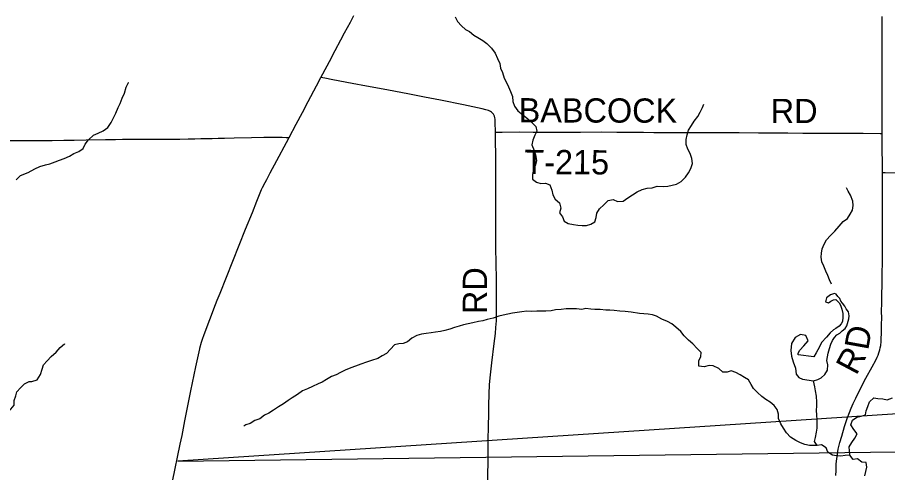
# Model space of a CAD drawing. Extents: x 0 to 34, y 0 to 22.
# Drawn here: x 15.659 to 17.698, y 13.231 to 14.297 of the extents above; entities that cross this region are included whole.
import ezdxf

# ---------------------------------------------------------------- set-up
doc = ezdxf.new("R2010")
doc.units = 0
for name, color, linetype in [('GM_X_County_Road', 7, 'Continuous'), ('GM_X_County_Road_Text', 7, 'Continuous'), ('GM_X_Minor_Lake', 7, 'Continuous'), ('GM_X_Minor_River', 7, 'Continuous'), ('GM_X_State_Route', 7, 'Continuous'), ('GM_X_Township_Road', 7, 'Continuous'), ('GM_X_Township_Road_Text', 7, 'Continuous'), ('SH_Text', 7, 'Continuous')]:
    doc.layers.add(name, color=color, linetype=linetype)

msp = doc.modelspace()

# ---------------------------------------------------------------- linework, layer by layer
at = {"layer": 'GM_X_County_Road'}
for points in [[(17.6856, 14.0251), (17.6855, 14.0542), (17.6855, 14.0673), (17.6855, 14.0716), (17.6854, 14.076), (17.6854, 14.0946), (17.6855, 14.1079), (17.6854, 14.1401), (17.6854, 14.1653), (17.6854, 14.1884), (17.6853, 14.205), (17.6856, 14.224), (17.6856, 14.2361), (17.6856, 14.2485), (17.6854, 14.2795), (17.6855, 14.2901), (17.6857, 14.2988)], [(15.6401, 14.0085), (15.6599, 14.0087), (15.6835, 14.0088), (15.722, 14.0087), (15.7407, 14.0087), (15.7674, 14.009), (15.7916, 14.0093), (15.8202, 14.0098), (15.8656, 14.0105), (15.8886, 14.0109), (15.9054, 14.0113), (15.9127, 14.0115), (15.9243, 14.0116), (15.9341, 14.0116), (15.9396, 14.0115), (15.952, 14.0115), (15.9731, 14.0118), (15.9849, 14.0119), (16.0115, 14.0118), (16.0394, 14.012), (16.0593, 14.0123), (16.0748, 14.0126), (16.0891, 14.0128), (16.1059, 14.0133), (16.1157, 14.0135), (16.1293, 14.0138), (16.1441, 14.014), (16.1667, 14.0144), (16.2076, 14.0153), (16.2363, 14.0161), (16.2595, 14.0161), (16.2794, 14.0161), (16.2887, 14.0157), (16.2956, 14.0153)], [(17.6863, 13.9338), (17.6861, 13.9531), (17.6861, 13.9654), (17.6858, 13.9772), (17.6858, 13.9921), (17.6857, 14.012), (17.6857, 14.0195), (17.6856, 14.0251)], [(17.5771, 13.224), (17.5774, 13.2353), (17.578, 13.2512), (17.579, 13.2628), (17.5805, 13.2738), (17.5826, 13.2859), (17.5864, 13.3009), (17.5906, 13.3162), (17.5976, 13.3389), (17.6037, 13.3578), (17.6089, 13.3715), (17.6132, 13.3819), (17.6178, 13.3924), (17.6238, 13.4048), (17.6302, 13.4183), (17.6473, 13.4522), (17.6619, 13.4788), (17.6704, 13.4938), (17.6739, 13.501), (17.676, 13.5059), (17.6779, 13.511), (17.6801, 13.518), (17.6812, 13.523), (17.6822, 13.5281), (17.6827, 13.5318), (17.6829, 13.5348), (17.6832, 13.5373), (17.6833, 13.5399), (17.6833, 13.5422), (17.6835, 13.5456), (17.6838, 13.5555), (17.6841, 13.5673), (17.6843, 13.5792), (17.6845, 13.5919), (17.6843, 13.6092), (17.6845, 13.6267), (17.6849, 13.6455), (17.6854, 13.6725), (17.6857, 13.6983), (17.686, 13.722), (17.6863, 13.7553), (17.6863, 13.7823), (17.6865, 13.8032), (17.6865, 13.8217), (17.6864, 13.8546), (17.6865, 13.873), (17.6865, 13.9084), (17.6863, 13.9326), (17.6863, 13.9338)]]:
    msp.add_lwpolyline(points, dxfattribs=at)
at = {"layer": 'GM_X_Minor_Lake'}
msp.add_line((17.4986, 13.4496), (17.5248, 13.4454), dxfattribs=at)
msp.add_lwpolyline([(17.5248, 13.4454), (17.5346, 13.4485), (17.5429, 13.4528), (17.5515, 13.4605), (17.5574, 13.4708), (17.5581, 13.483), (17.556, 13.4936), (17.5589, 13.5107), (17.5622, 13.521), (17.5655, 13.5313), (17.5695, 13.5404), (17.574, 13.5473), (17.5792, 13.5531), (17.5864, 13.5574), (17.592, 13.5627), (17.5988, 13.5685), (17.6029, 13.5746), (17.6039, 13.5803), (17.6072, 13.591), (17.6079, 13.5982), (17.6063, 13.6073), (17.6013, 13.6141), (17.5982, 13.6205), (17.5924, 13.6277), (17.5886, 13.6326), (17.5863, 13.6386), (17.582, 13.6435), (17.5778, 13.6484), (17.5736, 13.6502), (17.5691, 13.6483), (17.5646, 13.6467), (17.5612, 13.6444), (17.5552, 13.6401), (17.553, 13.631), (17.5595, 13.6284), (17.5651, 13.6319), (17.5715, 13.6354), (17.5772, 13.6362), (17.5848, 13.6287), (17.5876, 13.6227), (17.5907, 13.6132), (17.5935, 13.6034), (17.5932, 13.595), (17.5925, 13.5848), (17.5896, 13.579), (17.5847, 13.574), (17.5772, 13.5686), (17.5712, 13.5651), (17.5633, 13.5578), (17.5554, 13.5483), (17.5435, 13.5352), (17.5383, 13.5253), (17.5309, 13.5115), (17.5257, 13.502), (17.4889, 13.5065), (17.4884, 13.5106), (17.4922, 13.5175), (17.5023, 13.5279), (17.512, 13.5394), (17.5069, 13.5519), (17.4944, 13.5544), (17.4816, 13.5474), (17.4727, 13.5332), (17.4713, 13.5169), (17.4734, 13.5032), (17.4773, 13.4904), (17.4824, 13.4753), (17.4841, 13.4612), (17.4902, 13.4537), (17.4986, 13.4496)], dxfattribs=at)
at = {"layer": 'GM_X_Minor_River'}
for points in [[(16.6851, 14.298), (16.6905, 14.287), (16.6993, 14.2769), (16.7089, 14.2686), (16.7184, 14.2638), (16.7284, 14.2552), (16.7383, 14.25), (16.7497, 14.2429), (16.7592, 14.2358), (16.77, 14.2249), (16.7784, 14.2132), (16.7843, 14.2004), (16.7897, 14.1891), (16.7909, 14.1781), (16.796, 14.1679), (16.7999, 14.1546), (16.8053, 14.1444), (16.8096, 14.1338), (16.8143, 14.1229), (16.8193, 14.1112), (16.8198, 14.1002), (16.8237, 14.0892), (16.8314, 14.0783), (16.8437, 14.0685), (16.8544, 14.0599), (16.8643, 14.0509), (16.8739, 14.0412), (16.8759, 14.0306), (16.8715, 14.021), (16.8667, 14.0092), (16.8645, 13.9982), (16.8696, 13.9849), (16.8731, 13.9751), (16.8752, 13.9614), (16.8734, 13.9519), (16.8686, 13.9405), (16.8661, 13.9287), (16.8662, 13.918), (16.8757, 13.9106), (16.8852, 13.908), (16.8962, 13.9085), (16.9069, 13.9045), (16.9112, 13.8924), (16.9139, 13.881), (16.9193, 13.8712), (16.9293, 13.8626), (16.9325, 13.8501), (16.9295, 13.8394), (16.9365, 13.8296), (16.9404, 13.8198), (16.9499, 13.8138), (16.962, 13.8117), (16.9719, 13.8099), (16.9825, 13.8093), (16.9927, 13.8098), (17.0026, 13.8125), (17.0124, 13.818), (17.0156, 13.8283), (17.017, 13.8382), (17.023, 13.8481), (17.0331, 13.8577), (17.0432, 13.8677), (17.0549, 13.8705), (17.0652, 13.8657), (17.0785, 13.8662), (17.0894, 13.8739), (17.1112, 13.8879), (17.1229, 13.8941), (17.1349, 13.8969), (17.1467, 13.8978), (17.1584, 13.9013), (17.172, 13.9011), (17.1834, 13.9012), (17.2038, 13.906), (17.2143, 13.9122), (17.2248, 13.923), (17.2315, 13.9329), (17.2371, 13.9429), (17.2407, 13.9547), (17.2395, 13.9661)], [(15.6843, 13.9339), (15.6998, 13.942), (15.7118, 13.9475), (15.7247, 13.9518), (15.7352, 13.9542), (15.7477, 13.9589), (15.7579, 13.9621), (15.7684, 13.9664), (15.7809, 13.9715), (15.7914, 13.9784), (15.8031, 13.9831), (15.8132, 13.9897), (15.818, 14), (15.8259, 14.01), (15.8375, 14.0211), (15.8484, 14.0258), (15.8601, 14.0309), (15.8706, 14.0393), (15.8788, 14.0508), (15.884, 14.0619), (15.8892, 14.0726), (15.8951, 14.0856), (15.8996, 14.0955), (15.9043, 14.1077), (15.9095, 14.1196), (15.9139, 14.1333), (15.9191, 14.1443), (15.9198, 14.1447)], [(17.2395, 13.9661), (17.2355, 13.9778), (17.2298, 13.988), (17.2258, 13.999), (17.2261, 14.0111), (17.2282, 14.0214), (17.2315, 14.0328), (17.2386, 14.0435), (17.2453, 14.0539), (17.2535, 14.065), (17.2587, 14.0749), (17.2646, 14.0856), (17.2672, 14.0936)], [(15.6557, 13.9165), (15.6659, 13.9265), (15.6843, 13.9339)], [(17.5666, 13.6718), (17.5619, 13.6824), (17.558, 13.6926), (17.5533, 13.7028), (17.5487, 13.7141), (17.544, 13.7243), (17.5424, 13.7349), (17.543, 13.7444), (17.5448, 13.7551), (17.5492, 13.7654), (17.5552, 13.7761), (17.5645, 13.7857), (17.5746, 13.7964), (17.5847, 13.8076), (17.5941, 13.8187), (17.6039, 13.826), (17.6106, 13.836), (17.6158, 13.8455), (17.6172, 13.8562), (17.6167, 13.8661), (17.6112, 13.8804), (17.6062, 13.8902), (17.6019, 13.8974)], [(17.61, 13.2717), (17.5991, 13.2704), (17.5885, 13.2692), (17.5786, 13.2698), (17.5691, 13.2716), (17.5584, 13.2787), (17.5542, 13.2889), (17.5435, 13.296), (17.5333, 13.294), (17.5151, 13.2945), (17.5041, 13.2967), (17.4938, 13.3003), (17.4828, 13.3063), (17.4709, 13.3137), (17.461, 13.3242), (17.4544, 13.3348), (17.4479, 13.345), (17.4428, 13.3571), (17.4423, 13.3673), (17.4392, 13.3783), (17.4326, 13.3881), (17.4231, 13.396), (17.4131, 13.4019), (17.4036, 13.409), (17.3937, 13.418), (17.3837, 13.4274), (17.3787, 13.4372), (17.3725, 13.4478), (17.363, 13.4537), (17.353, 13.4597), (17.3428, 13.4653), (17.3317, 13.4689), (17.3219, 13.4658), (17.3121, 13.466), (17.3025, 13.4747), (17.2896, 13.4806), (17.2801, 13.4812), (17.268, 13.4788), (17.2555, 13.4802), (17.2561, 13.4923), (17.2609, 13.5027), (17.2616, 13.5122), (17.2516, 13.5212), (17.242, 13.5324), (17.2313, 13.5407), (17.2217, 13.5512), (17.2137, 13.5613), (17.2022, 13.5711), (17.1923, 13.5789), (17.1827, 13.5849), (17.169, 13.5904), (17.1565, 13.5968), (17.147, 13.6001), (17.1375, 13.6015), (17.1272, 13.6029), (17.117, 13.6035), (17.0973, 13.6063), (17.0832, 13.608), (17.0707, 13.609), (17.0575, 13.61), (17.0476, 13.611), (17.0378, 13.6113), (17.0245, 13.6131), (17.0124, 13.6129), (17.0029, 13.6136), (16.9911, 13.6149), (16.9813, 13.6129), (16.9695, 13.6139), (16.9582, 13.6146), (16.9453, 13.614), (16.9332, 13.6127), (16.92, 13.6118), (16.9101, 13.6094), (16.8973, 13.6089), (16.8761, 13.6087), (16.8647, 13.6082), (16.853, 13.6088), (16.8409, 13.6075), (16.8299, 13.6055), (16.8189, 13.6042), (16.8083, 13.6018), (16.7974, 13.5994), (16.7872, 13.597), (16.7736, 13.5927), (16.7596, 13.5891), (16.7498, 13.5863), (16.7392, 13.5847), (16.726, 13.5815), (16.7154, 13.5791), (16.7041, 13.5767), (16.6939, 13.5735), (16.6829, 13.5707), (16.672, 13.5668), (16.6607, 13.5632), (16.6505, 13.5612), (16.6388, 13.5599), (16.6289, 13.5583), (16.6172, 13.5563), (16.6059, 13.5546), (16.5949, 13.5518), (16.5832, 13.5456)], [(16.5832, 13.5456), (16.5731, 13.5372), (16.5629, 13.5332), (16.5531, 13.532), (16.5429, 13.5296), (16.5335, 13.52), (16.5242, 13.5096), (16.514, 13.5042), (16.5035, 13.498), (16.4891, 13.4936), (16.4767, 13.4897), (16.4635, 13.485), (16.451, 13.4799), (16.4401, 13.4764), (16.4273, 13.4705), (16.416, 13.4651), (16.4062, 13.46), (16.3949, 13.4557), (16.3836, 13.4484), (16.3734, 13.4422), (16.3636, 13.439), (16.3504, 13.4324), (16.3384, 13.4266), (16.3274, 13.4223), (16.315, 13.4134), (16.303, 13.4056), (16.2932, 13.3995), (16.2823, 13.3917), (16.2707, 13.3851), (16.259, 13.3767), (16.2485, 13.3701), (16.2383, 13.365), (16.2267, 13.3569), (16.2154, 13.3526), (16.2044, 13.346), (16.1939, 13.3425), (16.1898, 13.3394)], [(15.6929, 13.4438), (15.7049, 13.448), (15.7127, 13.4607), (15.7171, 13.4729), (15.7204, 13.4828), (15.7283, 13.4927), (15.738, 13.5027), (15.75, 13.5131), (15.7593, 13.5239), (15.7691, 13.5323), (15.7691, 13.5316)], [(15.4915, 13.3653), (15.535, 13.377), (15.5459, 13.3786), (15.5569, 13.3776), (15.5672, 13.3754), (15.5778, 13.3735), (15.5873, 13.3702), (15.6002, 13.3612), (15.6108, 13.3586), (15.621, 13.361), (15.6335, 13.369), (15.6436, 13.3793), (15.6511, 13.3889), (15.651, 13.3999), (15.6551, 13.4102), (15.6577, 13.42), (15.6659, 13.4296), (15.6757, 13.4384), (15.6866, 13.4438), (15.6929, 13.4438)], [(17.5333, 13.294), (17.5271, 13.3038), (17.5293, 13.3133), (17.5314, 13.3251), (17.5328, 13.335), (17.5331, 13.3448), (17.5334, 13.3543), (17.5321, 13.365), (17.532, 13.3767), (17.5326, 13.3862), (17.5325, 13.3957), (17.5316, 13.4101), (17.5296, 13.4219), (17.5276, 13.4317), (17.5248, 13.4454)], [(17.645, 13.2235), (17.6472, 13.233), (17.6494, 13.2437), (17.6477, 13.2547), (17.6379, 13.2553), (17.6276, 13.2628), (17.6177, 13.2615), (17.61, 13.2717), (17.6088, 13.2816), (17.6083, 13.291), (17.6142, 13.3014), (17.6213, 13.3113), (17.6273, 13.3216), (17.6192, 13.3318), (17.6119, 13.3427), (17.6159, 13.3534), (17.6265, 13.3604), (17.6363, 13.3628), (17.6465, 13.3659), (17.6479, 13.3754), (17.6516, 13.3853), (17.656, 13.3968), (17.6657, 13.4056), (17.6752, 13.4042), (17.687, 13.4032), (17.6972, 13.4014), (17.71, 13.4058)]]:
    msp.add_lwpolyline(points, dxfattribs=at)
at = {"layer": 'GM_X_State_Route'}
msp.add_lwpolyline([(16.022, 13.21), (16.0404, 13.297), (16.0447, 13.3177), (16.0516, 13.3518), (16.0657, 13.4225), (16.0769, 13.4784), (16.0863, 13.5204), (16.0866, 13.5219), (16.0907, 13.5363), (16.0929, 13.5434), (16.0967, 13.554), (16.1232, 13.6243), (16.127, 13.6342), (16.1337, 13.6509), (16.1784, 13.763), (16.1938, 13.8009), (16.2096, 13.84), (16.22, 13.8666), (16.2264, 13.8821), (16.2312, 13.8936), (16.2334, 13.8987), (16.2394, 13.9103), (16.2433, 13.9174), (16.2475, 13.925), (16.2516, 13.9326), (16.2671, 13.9616), (16.2896, 14.0039), (16.2956, 14.0153), (16.3122, 14.0468), (16.3269, 14.0742), (16.3407, 14.0999), (16.3597, 14.1362), (16.3703, 14.1559), (16.375, 14.1646), (16.39, 14.1932), (16.4039, 14.2196), (16.4171, 14.2443), (16.4258, 14.2608), (16.4392, 14.2859), (16.4475, 14.3013)], dxfattribs=at)
at = {"layer": 'GM_X_Township_Road'}
for points in [[(16.7794, 14.0282), (16.7792, 14.0343), (16.7789, 14.0455), (16.7789, 14.0486), (16.7787, 14.0587), (16.778, 14.0618), (16.777, 14.0655), (16.7744, 14.0699), (16.7732, 14.0715), (16.7699, 14.0746), (16.7673, 14.0763), (16.7627, 14.0787), (16.7567, 14.0807), (16.7482, 14.0828), (16.7043, 14.0919), (16.6501, 14.103), (16.6129, 14.1101), (16.5776, 14.1172), (16.525, 14.1272), (16.4773, 14.1359), (16.4438, 14.1422), (16.398, 14.1508), (16.3797, 14.1541), (16.3703, 14.1559)], [(16.7609, 13.1906), (16.762, 13.2577), (16.7624, 13.3062), (16.763, 13.3403), (16.7636, 13.3677), (16.7637, 13.3876), (16.7644, 13.4155), (16.7654, 13.436), (16.7668, 13.4527), (16.7706, 13.4879), (16.7762, 13.5329), (16.7791, 13.5563), (16.7805, 13.5706), (16.7814, 13.5861), (16.7816, 13.6029), (16.7817, 13.6322), (16.7818, 13.6527), (16.7817, 13.6838), (16.7811, 13.7211), (16.7805, 13.7571), (16.78, 13.7969), (16.7801, 13.8254), (16.78, 13.8615), (16.7801, 13.9025), (16.7802, 13.9361), (16.7802, 13.9497), (16.7798, 13.9783), (16.7797, 14.0038), (16.7796, 14.0225), (16.7794, 14.0282)], [(16.7794, 14.0282), (16.7845, 14.0283), (16.7948, 14.0284), (16.8346, 14.0285), (16.8676, 14.0284), (16.9077, 14.0284), (16.9419, 14.0281), (16.9786, 14.0283), (17.0289, 14.0285), (17.0637, 14.0283), (17.1066, 14.028), (17.1258, 14.0277), (17.1501, 14.0273), (17.1725, 14.0274), (17.216, 14.0273), (17.2365, 14.0274), (17.2489, 14.0275), (17.302, 14.0273), (17.3507, 14.027), (17.3957, 14.0266), (17.4284, 14.0262), (17.4644, 14.0262), (17.4998, 14.0259), (17.5526, 14.0258), (17.5652, 14.0256), (17.5917, 14.0256), (17.6172, 14.0255), (17.6407, 14.0255), (17.6807, 14.0251), (17.6856, 14.0251)], [(17.6863, 13.9338), (17.6922, 13.9337), (17.7627, 13.9329), (17.8726, 13.9318), (17.8799, 13.9311), (17.887, 13.9296), (17.8904, 13.9283), (17.8943, 13.9267), (17.9002, 13.9233), (17.9053, 13.9198), (17.9113, 13.9154), (17.9144, 13.9129)]]:
    msp.add_lwpolyline(points, dxfattribs=at)
at = {"layer": 'SH_Text'}
msp.add_lwpolyline([(20.9048, 13.5772), (16.0348, 13.2578), (20.9048, 13.3206)], close=True, dxfattribs=at)

# ---------------------------------------------------------------- texts
at = {"layer": 'GM_X_County_Road_Text'}
for s, rotation, p in [('D', 79.8842, (17.6526, 13.5156)), ('R', 62.1013, (17.6247, 13.4565))]:
    msp.add_text(s, height=0.0568, rotation=rotation, dxfattribs=at).set_placement(p)
at = {"layer": 'GM_X_Township_Road_Text'}
for s, rotation, p in [('BABCOCK', 359.8583, (16.8335, 14.0509)), ('RD', 0, (17.4244, 14.0492)), ('T-215', 359.7181, (16.8469, 13.9299)), ('RD', 90, (16.7595, 13.6019))]:
    msp.add_text(s, height=0.05682, rotation=rotation, dxfattribs=at).set_placement(p)

doc.saveas('drawing.dxf')
